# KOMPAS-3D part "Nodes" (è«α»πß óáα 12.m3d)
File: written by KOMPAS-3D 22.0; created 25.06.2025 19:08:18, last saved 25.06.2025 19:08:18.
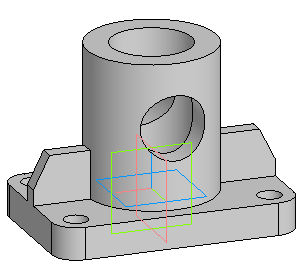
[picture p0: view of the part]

Document properties: Автор: Helen; Полное имя файла: D:\MY\WORK\MPEI\ППЭ_2025-2026\Варианты\Вар 12 СБ\Корпус вар 12.m3d

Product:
- Part/product: Nodes

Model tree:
1. Операция без истории:1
